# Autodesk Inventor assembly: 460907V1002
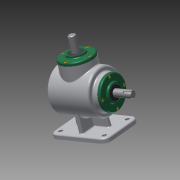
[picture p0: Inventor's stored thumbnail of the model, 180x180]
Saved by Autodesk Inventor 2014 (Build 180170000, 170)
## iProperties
Created: 2016-09
Part Number: 460907V1002
Document SubType Name: Assembly
Designer: 702
Author: 702
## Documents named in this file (14)
- C:\Users\702\Desktop\460907V1002.iam
- C:\Users\702\Desktop\460907V1002. 본체.ipt
- C:\Users\702\Desktop\M4.ipt
- C:\Users\702\Desktop\메인 베벨기어.ipt
- C:\Users\702\Desktop\메인 축.ipt
- 메인 축.ipt
- C:\Users\702\Desktop\베어링 6203.ipt
- C:\Users\702\Desktop\서브 베벨기어.ipt
- C:\Users\702\Desktop\서브 축.ipt
- 서브 축.ipt
- C:\Users\702\Desktop\오일실 17 32 8.ipt
- C:\Users\702\Desktop\커버.ipt
- C:\Users\702\Desktop\키 4x4.ipt
- C:\Users\702\Desktop\키 5x5.ipt
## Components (9 placed, 2 different names)
1. 460907V1002. 본체:1
2. M4:2
3. M4:3
4. M4:4
5. M4:5
6. M4:1
7. M4:6
8. M4:7
9. M4:8
